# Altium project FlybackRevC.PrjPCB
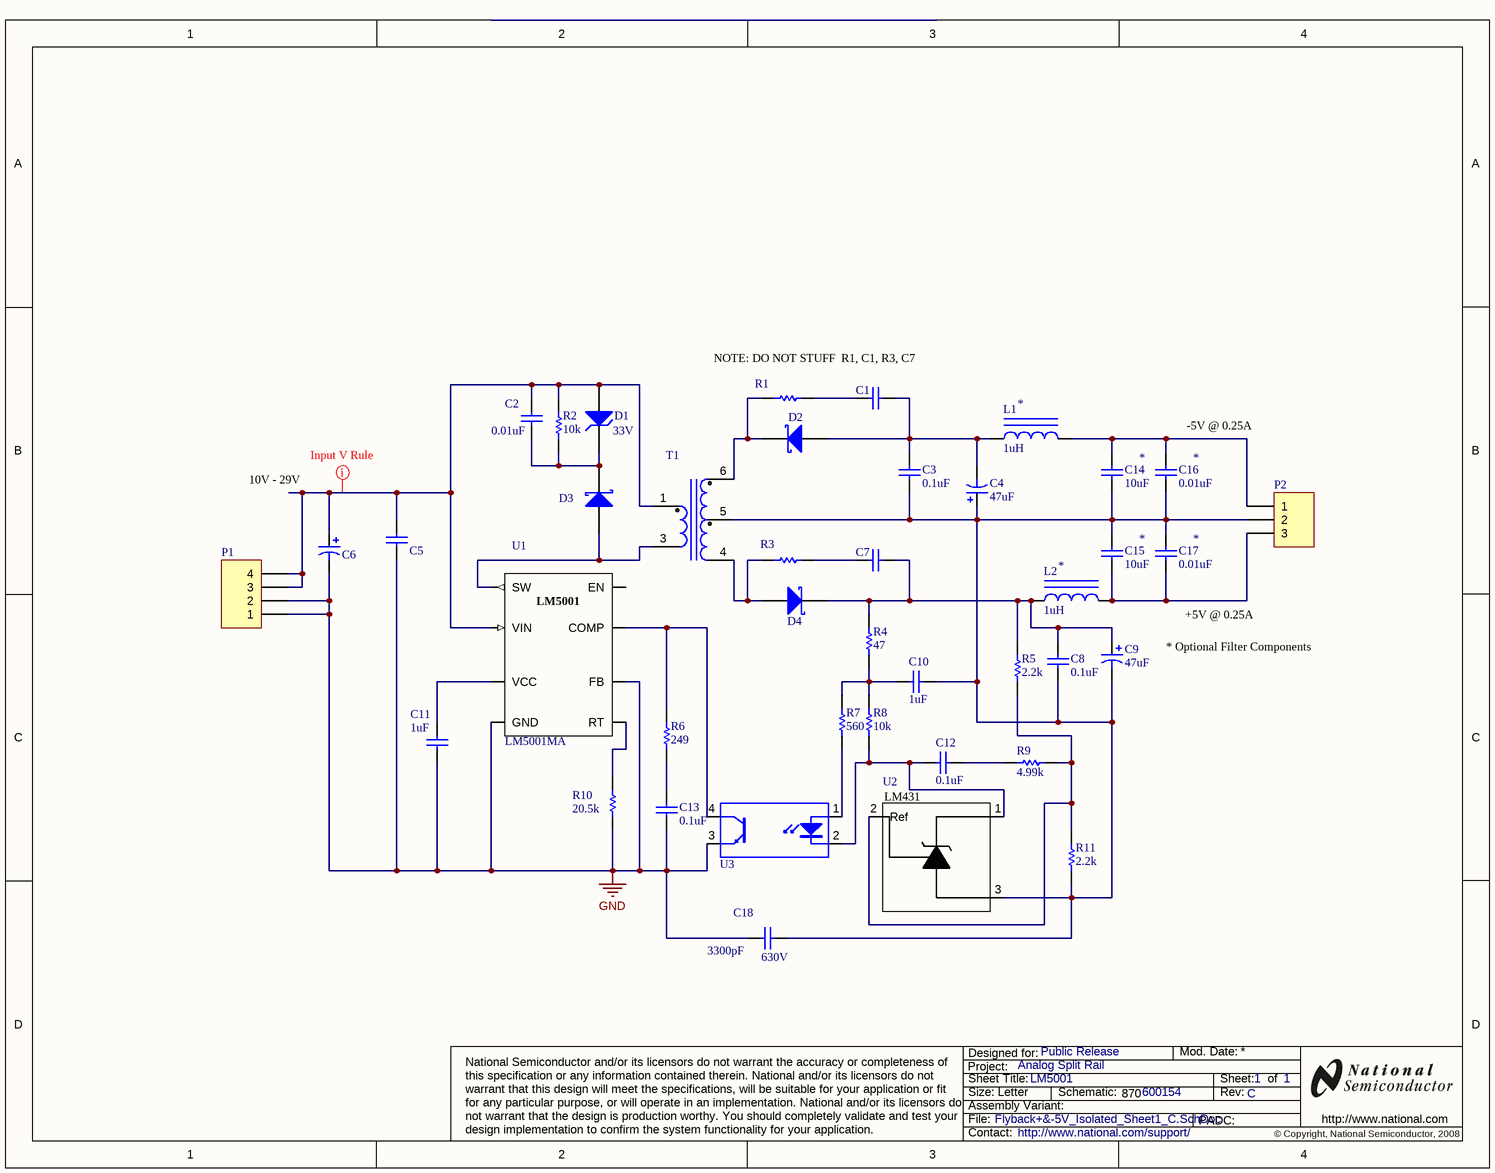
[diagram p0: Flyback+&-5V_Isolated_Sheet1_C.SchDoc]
PRJ_BasePN: 600154; PRJ_Customer: Public Release; PRJ_Title: Analog Split Rail; SCH_Rev: C
1 sheet, 41 parts. Net scope: global (net labels, ports and power ports of the same name join across sheets).
Board file: Split Rail RevC.PcbDoc

## Sheet Flyback+&-5V_Isolated_Sheet1_C.SchDoc: LM5001
size Letter; Author: R. H.; Organization: National Semiconductor; Address1: 2900 Semiconductor Dr.; Address3: Santa Clara, CA  95051; Address4: United States; Revision: XP-1; SheetNumber: 1; SheetTotal: 1; TechSupport: http://www.national.com/support/; PageSetup: Record=PageOptions|CenterHorizontal=True|CenterVertical=True|PrintScale=0.94|XCorrection=1.00|YCorrection=1.00|PrintKind=0|BorderSize=5000000|LeftOffset=0|BottomOffset=0|Orientation=2|PaperLength=1000|PaperWidth=1000|Scale=100|PaperSource=7|PrintQuality=-4|MediaType=1|DitherType=10|PaperKind=Letter 8.5 x 11in|PrintScaleMode=1

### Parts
C1  06035A221JAT2A  [0603]  (value not drawn)
C2  value 0.01uF  [0603]  (hidden comment: GRM188R71H103KA01D)
C3  value 0.1uF  [0805]  (hidden comment: C0805C104J5RACTU)
C4  value 47uF  [SM_RADIAL_D]  (hidden comment: EEE-FK1C470P)
C5  C0805C104J5RACTU  [0805]  (value not drawn)
C6  EMZA500ADA100ME61G  [MZA]  (value not drawn)
C7  06035A221JAT2A  [0603]  (value not drawn)
C8  value 0.1uF  [0805]  (hidden comment: C0805C104J5RACTU)
C9  value 47uF  [SM_RADIAL_D]  (hidden comment: EEE-FK1C470P)
C10  value 1uF  [0805]  (hidden comment: TMK212BJ105KG-T)
C11  value 1uF  [1210]  (hidden comment: GRM32RR71H105KA01L)
C12  value 0.1uF  [0805]  (hidden comment: C0805C104J5RACTU)
C13  value 0.1uF  [0805]  (hidden comment: C0805C104J5RACTU)
C14  value 10uF  [0805]  (hidden comment: EMK212BJ106KG-T)
C15  value 10uF  [0805]  (hidden comment: EMK212BJ106KG-T)
C16  value 0.01uF  [0603]  (hidden comment: C1608X7R1H103K)
C17  value 0.01uF  [0603]  (hidden comment: C1608X7R1H103K)
C18  value 3300pF  Value2: 630V  [1206]  (hidden comment: C3216C0G2J332J)
D1  Vz: 33V  [SMB]  (hidden comment: 1SMB5937BT3G)
D2  1N5819HW-7-F  [SOD-123]  (value not drawn)
D3  BAT41ZFILM  [SOD-123]  (value not drawn)
D4  1N5819HW-7-F  [SOD-123]  (value not drawn)
L1  value 1uH  [ME3220]  (hidden comment: ME3220-102MLB)
L2  value 1uH  [ME3220]  (hidden comment: ME3220-102MLB)
P1  Header 4  [HDR1X4]  (value not drawn)
P2  Header 3  [HDR1X3]  (value not drawn)
R1  CRCW0603120RJNEA  [0603]  (value not drawn)
R2  value 10k  [0603]  (hidden comment: CRCW060310k0JNEA)
R3  CRCW0603120RJNEA  [0603]  (value not drawn)
R4  value 47  [0603]  (hidden comment: CRCW060347R0JNEA)
R5  value 2.2k  [0603]  (hidden comment: CRCW06032k20JNEA)
R6  value 249  [0603]  (hidden comment: CRCW0603249RFKEA)
R7  value 560  [0603]  (hidden comment: CRCW0603560RJNEA)
R8  value 10k  [0603]  (hidden comment: CRCW060310k0JNEA)
R9  value 4.99k  [0603]  (hidden comment: CRCW06034k99FKEA)
R10  value 20.5k  [0603]  (hidden comment: CRCW060320k5FKEA)
R11  value 2.2k  [0603]  (hidden comment: CRCW06032k20JNEA)
T1  RL-8800  [S32890]  (value not drawn)
U1  LM5001MA  [M08A]
U2  LM431Z  [MF03A]  (value not drawn)
U3  FODM121  [FOD121]  (value not drawn)

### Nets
GND: C5.2 C6.2(-) C11.2 C13.2 C18.2 P1.1 P1.2 R10.1 U1.4(GND) U1.6(FB) U3.3(E)
NetC1_1: C1.1 C3.1 C4.2(-) D2.1(A) L1.1
NetC1_2: C1.2 R1.1
NetC2_1: C2.1 C5.1 C6.1(+) D1.1(A) P1.3 P1.4 R2.1 T1.1 U1.2(VIN)
NetC2_2: C2.2 D1.2(K) D3.2(K) R2.2
NetC3_2: C3.2 C4.1(+) C8.2 C9.2(-) C10.1 C14.2 C15.1 C16.2 C17.1 C18.1 P2.2 R11.1 T1.5 U2.3(Anode)
NetC7_1: C7.1 C8.1 C9.1(+) D4.2(K) L2.1 R4.2 R5.1
NetC7_2: C7.2 R3.1
NetC10_2: C10.2 R4.1 R7.2 R8.2
NetC11_1: C11.1 U1.3(VCC)
NetC12_1: C12.1 R8.1 U2.1(Cathode) U3.2(K)
NetC12_2: C12.2 R9.2
NetC13_1: C13.1 R6.2
NetC14_1: C14.1 C16.1 L1.2 P2.1
NetC15_2: C15.2 C17.2 L2.2 P2.3
NetD2_2: D2.2(K) R1.2 T1.6
NetD3_1: D3.1(A) T1.3 U1.1(SW)
NetD4_1: D4.1(A) R3.2 T1.4
NetR5_2: R5.2 R9.1 R11.2 U2.2(Ref)
NetR6_1: R6.1 U1.7(COMP) U3.4(C)
NetR7_1: R7.1 U3.1(A)
NetR10_2: R10.2 U1.5(RT)

Not connected (* = marked no-connect by the designer): T1 2; U1 8(EN)

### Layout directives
rule Width Constraint [Pref Width = 40mil    Min Width = 10mil    Max Width = 100mil]: NetC2_1

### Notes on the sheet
- NOTE: DO NOT STUFF  R1, C1, R3, C7
- (near L1) *
- (near C16) -5V @ 0.25A
- 10V - 29V
- *
- (near C16) *
- (near L2) *
- (near C17) *
- * Optional Filter Components
- +5V @ 0.25A

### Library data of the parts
C1 C7 = 06035A221JAT2A: Capacitor; Manufacturer: AVX; Value: 220pF; Value2: 50V; Value1: 0.083Ohm; Polarized: N; Cap_F: 220.0E-12; Characteristics: Ceramic, C0G/NP0, 50V, 5%; Dielectric: C0G/NP0; ESR_Ohm: 0.083; TaMax_C: 125; TaMin_C: -55; Tolerance_%: 5; VDC_V: 50
C2 = GRM188R71H103KA01D: Capacitor; Manufacturer: MuRata; Value2: 50V; Value1: Ohm; Polarized: N; Cap_F: 10.0E-9; Characteristics: Ceramic, X7R, 50V, 10%; Dielectric: X7R; TaMax_C: 125; TaMin_C: -55; Tolerance_%: 10; VDC_V: 50
C3 C8 = C0805C104J5RACTU: Capacitor; Manufacturer: Kemet; Polarized: N; Cap_F: 100.0E-9; Characteristics: Ceramic, X7R, 50V, 5%; Dielectric: X7R; ESR_Ohm: 0.064; IRMS_A: 1.64; TaMax_C: 125; TaMin_C: -55; Tolerance_%: 5; Value1: 0.064Ohm; Value2: 50V; VDC_V: 50
C4 C9 = EEE-FK1C470P: Polarized Capacitor; Manufacturer: Panasonic; Cap_Case: D; Value2: 16V; Value1: 0.36Ohm; Polarized: Y; ESR_Ohm: 0.36; IRMS_A: 0.24; TaMax_C: 105; TaMin_C: -55; Tolerance_%: 20; VDC_V: 16; Cap_F: 47.0E-6; Characteristics: AL, 16V, 20%, 0.36Ohm ESR; Dielectric: FK
C5 = C0805C104J5RACTU: Capacitor; Manufacturer: Kemet; Value: 0.1uF; Polarized: N; Cap_F: 100.0E-9; Characteristics: Ceramic, X7R, 50V, 5%; Dielectric: X7R; ESR_Ohm: 0.064; IRMS_A: 1.64; TaMax_C: 125; TaMin_C: -55; Tolerance_%: 5; Value1: 0.064Ohm; Value2: 50V; VDC_V: 50
C6 = EMZA500ADA100ME61G: Polarized Capacitor; Manufacturer: Nippon Chemi-Con; Cap_Case: E61; Value: 10uF; Value2: 50V; Value1: Ohm; Polarized: Y; Cap_F: 10.0E-6; Characteristics: AL, 50V, 20%; IRMS_A: 0.085; TaMax_C: 105; TaMin_C: -55; Tolerance_%: 20; VDC_V: 50
C10 = TMK212BJ105KG-T: Capacitor; Manufacturer: Taiyo Yuden; Polarized: N; Cap_F: 1.0E-6; Characteristics: Ceramic, X5R, 20V, 10%; Dielectric: X5R; TaMax_C: 85; TaMin_C: -55; Tolerance_%: 10; Value1: Ohm; Value2: 20V; VDC_V: 20
C11 = GRM32RR71H105KA01L: Capacitor; Manufacturer: MuRata; Polarized: N; TaMax_C: 85; TaMin_C: -30; Tolerance_%: 10; VDC_V: 50; Cap_F: 1.0E-6; Characteristics: Ceramic, X7R, 50V, 10%; Value1: Ohm; Value2: 50V; Dielectric: X7R
C12 C13 = C0805C104J5RACTU: Capacitor; Manufacturer: Kemet; Polarized: N; Value1: 0.064Ohm; Value2: 50V; Dielectric: X7R; Cap_F: 100.0E-9; Characteristics: Ceramic, X7R, 50V, 5%; ESR_Ohm: 0.064; IRMS_A: 1.64; TaMax_C: 125; TaMin_C: -55; Tolerance_%: 5; VDC_V: 50
C14 C15 = EMK212BJ106KG-T: Capacitor; Manufacturer: Taiyo Yuden; Polarized: N; Value1: Ohm; Value2: 16V; Dielectric: X5R; Cap_F: 10.0E-6; Characteristics: Ceramic, X5R, 16V, 10%; TaMax_C: 85; TaMin_C: -55; Tolerance_%: 10; VDC_V: 16
C16 C17 = C1608X7R1H103K: Capacitor; Manufacturer: TDK; Polarized: N; Value1: 0.0539Ohm; Value2: 50V; Dielectric: X7R; Cap_F: 10.0E-9; Characteristics: Ceramic, X7R, 50V, 10%; ESR_Ohm: 0.0539; TaMax_C: 125; TaMin_C: -55; Tolerance_%: 10; VDC_V: 50
C18 = C3216C0G2J332J: Capacitor; Manufacturer: TDK; Polarized: N; Value1: 0.0369Ohm; Dielectric: C0G/NP0; Cap_F: 3.3E-9; Characteristics: Ceramic, C0G/NP0, 630V, 5%; ESR_Ohm: 0.0369; TaMax_C: 125; TaMin_C: -55; Tolerance_%: 5; VDC_V: 630
D1 = 1SMB5937BT3G: Manufacturer: ON Semiconductor; CompType: Zener; Value: 33V; Power_W: 0.55; RJA_CperW: 226
D2 D4 = 1N5819HW-7-F: Schottky Diode; Manufacturer: Diodes Inc.; Value: 0.45V; Vf_V: 0.45; Io_A: 1; Vr_V: 40; TJMax_C: 125; Characteristics: Vr = 40V, Io = 1A, Vf = 0.45V; Value1: 1A; Value2: 40V
D3 = BAT41ZFILM: Schottky Diode; Manufacturer: ST Microelectronics; Value: 1V; Vf_V: 1; Io_A: 0.2; Vr_V: 100; TJMax_C: 150; Characteristics: Vr = 100V, Io = 0.2A, Vf = 1V; Value1: 0.2A; Value2: 100V
L1 L2 = ME3220-102MLB: Magnetic-Core Inductor; Manufacturer: Coilcraft Inc.; Value1: 0.058Ohm; Value2: 2.7A; Material: Ferrite; Characteristics: Unshielded Drum Core, 2.7A, 0.058 Ohm; DCR_Ohm: 0.058; Imax_A: 2.7; Ind_H: 1.0E-6
P1 = Header 4: Header, 4-Pin; Manufacturer_PN: 90120-0124; Manufacturer: Molex; Value: 1x4
P2 = Header 3: Header, 3-Pin; Manufacturer_PN: 90120-0123; Manufacturer: Molex; Value: 1x3
R1 R3 = CRCW0603120RJNEA: Resistor; Manufacturer: Vishay-Dale; Value: 120; Value_Code: 120R; Value1: 5%; Value2: 0.1W; Characteristics: 5%, 0.1W; EIA_Code: E24; Power_W: 0.1; Tolerance_%: 5; VDC_V: 75
R2 R8 = CRCW060310k0JNEA: Resistor; Manufacturer: Vishay-Dale; Value_Code: 10k0; Value1: 5%; Value2: 0.1W; Characteristics: 5%, 0.1W; EIA_Code: E24; Power_W: 0.1; Res_Ohm: 10000; Tolerance_%: 5; VDC_V: 75
R4 = CRCW060347R0JNEA: Resistor; Manufacturer: Vishay-Dale; Value_Code: 47R0; Value1: 5%; Value2: 0.1W; Characteristics: 5%, 0.1W; EIA_Code: E24; Power_W: 0.1; Tolerance_%: 5; VDC_V: 75
R5 R11 = CRCW06032k20JNEA: Resistor; Manufacturer: Vishay-Dale; Value_Code: 2k20; Value1: 5%; Value2: 0.1W; Characteristics: 5%, 0.1W; EIA_Code: E24; Power_W: 0.1; Res_Ohm: 2200; Tolerance_%: 5; VDC_V: 75
R6 = CRCW0603249RFKEA: Resistor; Manufacturer: Vishay-Dale; Value_Code: 249R; Value1: 1%; Value2: 0.1W; Characteristics: 1%, 0.1W; EIA_Code: E96; Power_W: 0.1; Tolerance_%: 1; VDC_V: 75
R7 = CRCW0603560RJNEA: Resistor; Manufacturer: Vishay-Dale; Value_Code: 560R; Value1: 5%; Value2: 0.1W; Characteristics: 5%, 0.1W; EIA_Code: E24; Power_W: 0.1; Tolerance_%: 5; VDC_V: 75
R9 = CRCW06034k99FKEA: Resistor; Manufacturer: Vishay-Dale; Value_Code: 4k99; Value1: 1%; Value2: 0.1W; Characteristics: 1%, 0.1W; EIA_Code: E96; Power_W: 0.1; Res_Ohm: 4990; Tolerance_%: 1; VDC_V: 75
R10 = CRCW060320k5FKEA: Resistor; Manufacturer: Vishay-Dale; Value_Code: 20k5; Value1: 1%; Value2: 0.1W; Characteristics: 1%, 0.1W; EIA_Code: E96; Power_W: 0.1; Res_Ohm: 20500; Tolerance_%: 1; VDC_V: 75
T1 = RL-8800: Transformer; Manufacturer: Renco Electronics, INC.; LeakageL: 0.84; Lp: 27.6
U1 = LM5001MA: High Voltage Switch Mode Regulator; Manufacturer: National Semiconductor; CompType: Switcher; base_pn: LM5001
U2 = LM431CCM3: Adjustable Precision Zener Shunt Regulator; Manufacturer: National Semiconductor; base_pn: LM431; CompType: Voltage Reference
U3 = FODM121: Full Pitch Mini-Flat Package Transistor Output  Optocoupler; Manufacturer: Fairchild Semiconductor

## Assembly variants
Assembled: not fitted C1 C7 R1 R3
